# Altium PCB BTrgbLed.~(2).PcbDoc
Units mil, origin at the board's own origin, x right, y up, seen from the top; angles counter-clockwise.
Board outline 6000 x 4000 mil, 2 copper layers (Top Layer, Bottom Layer); 13 components, 12 nets, 36 pads, 0 vias.
Unrouted connection lines stored in the file: 22.
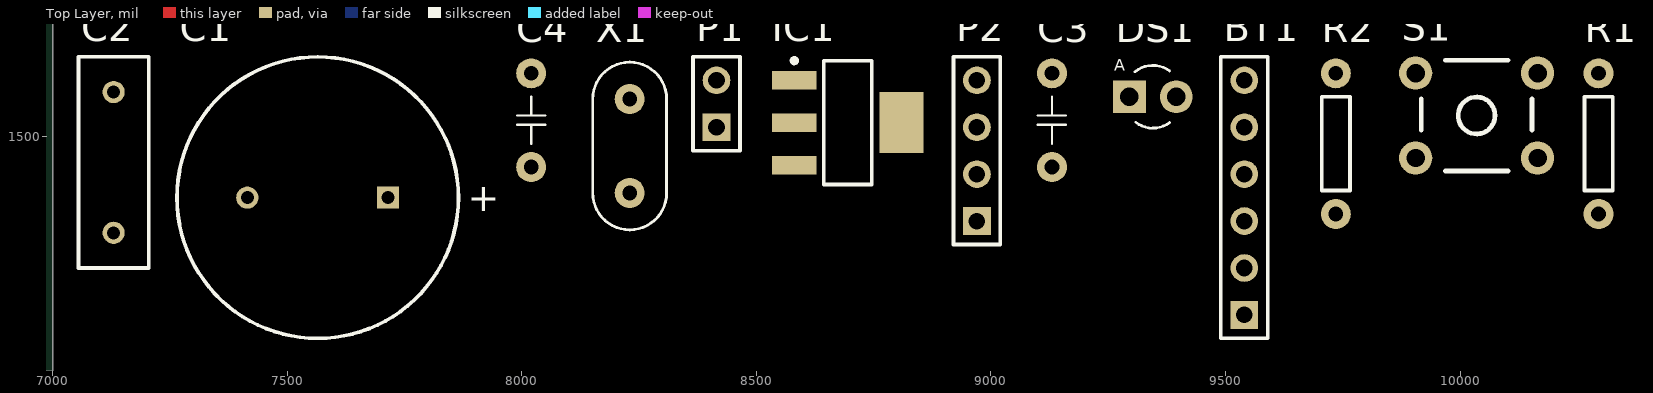
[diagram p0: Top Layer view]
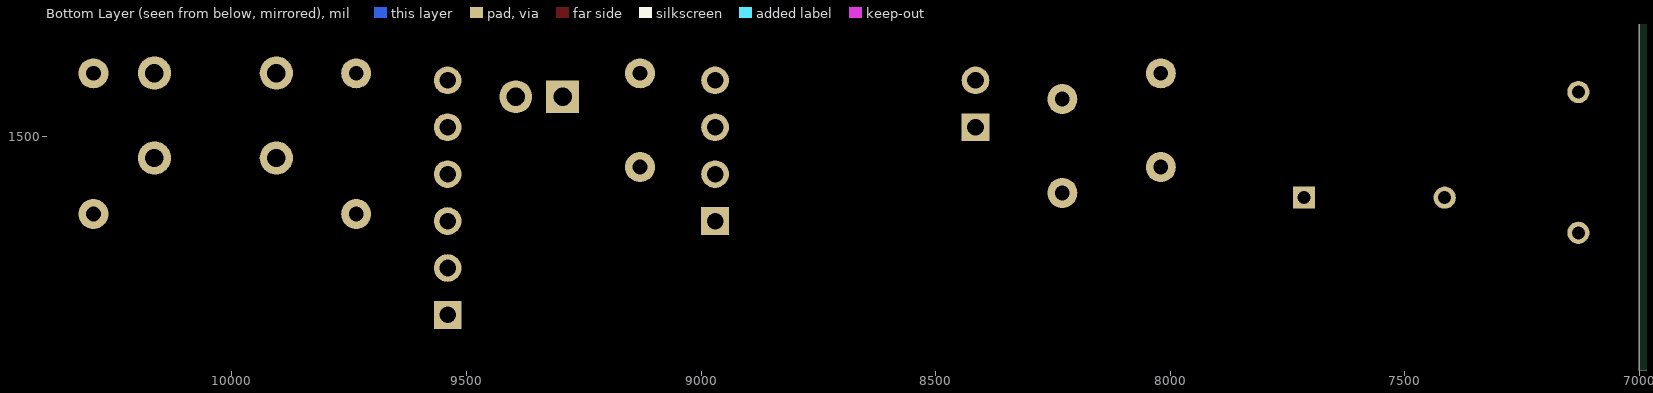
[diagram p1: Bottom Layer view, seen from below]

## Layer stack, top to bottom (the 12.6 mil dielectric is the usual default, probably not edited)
Top Layer: signal copper 1.4
Dielectric: dielectric 12.6, FR-4, Dk 4.8
Bottom Layer: signal copper 1.4

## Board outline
1000,1000 7000,1000 7000,5000 1000,5000

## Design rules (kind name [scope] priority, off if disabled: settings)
Clearance [All] p1: gap=10
PolygonConnect [All] p1: connectstyle=Relief reliefconductorwidth=10 reliefentries=4 polygonreliefangle="90 Angle"
RoomDefinition BTrgbLed [InComponentClass('BTrgbLed')] p1: confinementstyle=ConfineIn formatcopy=TRUE lockcomponents=FALSE outline 7045,1060 10365,1060 10365,1780 7045,1780
RoutingVias [All] p1: holewidth=28 width=50 viastyle="Through Hole" minholewidth=28 minwidth=50 maxholewidth=28 maxwidth=50
SilkscreenOverComponentPads [All] p1: minsilkscreentomaskgap=10
SolderMaskExpansion [All] p1: expansion=4
Width [All] p1: maxlimit=10 minlimit=10 preferedwidth=10
27 further rules are at their usual default settings.

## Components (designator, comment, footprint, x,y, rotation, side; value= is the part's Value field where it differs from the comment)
BT1 "Bluetooth" Bluetooth 9540,1120 r90 top
C1 "47uF" RB7.6-15 7565,1370 r0 top
C2 "Cap" RAD-0.3 7130,1445 r90 top
C3 "22pF" C200 9130,1535 r0 top
C4 "22pF" C200 8020,1535 r0 top
DS1 "TX-LED" LED-3mm_G 9345,1585 r0 top
IC1 "AM1117-5V" SOT-223 8695,1530 r0 top
P1 "12V" HDR1X2 8415,1520 r90 top
P2 "環形LED燈" HDR1X4 8970,1320 r90 top
R1 "10k" AXIAL-0.3 10295,1485 r90 top
R2 "220" AXIAL-0.3 9735,1485 r90 top
S1 "SW-PB" TACK6 10035,1545 r0 top
X1 "16MHz" XTAL4-8 8230,1480 r90 top

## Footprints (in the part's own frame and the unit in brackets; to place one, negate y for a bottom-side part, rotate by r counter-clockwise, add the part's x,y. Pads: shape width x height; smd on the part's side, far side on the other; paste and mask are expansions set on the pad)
AXIAL-0.3 [mil] "0.3\" Resistor; 2 Leads"
  round 64 hole 31.5: 1(-150,0) 2(150,0)
  silkscreen extent -100,-30 100,30, body extent -161,-39 165,39, height 86
Bluetooth [mm]
  rect 1.5x1.5 hole 0.9: 1(0,0)
  round 1.5 hole 0.9: 2(2.54,0) 3(5.08,0) 4(7.62,0) 5(10.16,0) 6(12.7,0)
  silkscreen extent -1.27,-1.27 13.97,1.27, body extent -1.25,-1.3 13.97,1.28, height 11
C200 [mil] "塑膠電容器"
  round 64 hole 31.5: 1(0,100) 2(0,-100)
  silkscreen extent -30,-50 30,50, body extent -41,-136 39,135, height 354
HDR1X2 [mm] "Connector; Header; 2 Position"
  rect 1.5x1.5 hole 0.9: 1(0,0)
  round 1.5 hole 0.9: 2(2.54,0)
  silkscreen extent -1.27,-1.27 3.81,1.27
HDR1X4 [mm] "Connector; Header; 4 Position"
  rect 1.5x1.5 hole 0.9: 1(0,0)
  round 1.5 hole 0.9: 2(2.54,0) 3(5.08,0) 4(7.62,0)
  silkscreen extent -1.27,-1.27 8.89,1.27
LED-3mm_G [mil] "3mm LED_Green"
  rect 70x70 hole 39: 1(-50,0)
  round 70 hole 39: 2(50,0)
  silkscreen extent -38,-67 35,67, body extent -66,-68 67,66, height 181
RAD-0.3 [mm] "Radial Cap, Thru-Hole; 2 Leads; 0.3 in Pin Spacing"
  round 1.2 hole 0.7: 1(-3.81,0) 2(3.81,0)
  silkscreen extent -5.71,-1.91 5.71,1.91
RB7.6-15 [mm] "Polarized Capacitor (Radial); 2 Leads"
  rect 1.2x1.2 hole 0.7: 1(3.81,0)
  round 1.2 hole 0.7: 2(-3.81,0)
  silkscreen extent -7.62,-7.62 7.62,7.62
SOT-223 [mm] "SOT223, 4-Leads, Body 6.7x7.3mm (max), Pitch 2.30mm, IPC Medium Density"
  rect 2.4x1 smd: 1(-2.9,2.3) 2(-2.9,0) 3(-2.9,-2.3)
  rect 2.4x3.3 smd: 2(2.9,0)
  silkscreen extent -3.02,-3.35 1.3,3.47, body extent -1.86,-3.35 1.86,3.35, height 1.8
TACK6 [mm]
  round 1.8 hole 1: 1(-3.3,2.3) 1(3.3,2.3) 2(-3.3,-2.3) 2(3.3,-2.3)
  silkscreen extent -3,-3 3,3, body extent -3,-3.01 3.08,3.04, height 8
XTAL4-8 [mil]
  round 64 hole 31.5: 1(-100,0) 2(100,0)
  silkscreen extent -179,-79 179,79, body extent -178,-80 192,79, height 157

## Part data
C1: library part "Cap Pol1", "Polarized Capacitor (Radial)"
C2: "Capacitor"
C3 C4: library part Cap, "Capacitor"
DS1: library part LED, "Typical INFRARED GaAs LED"
IC1: library part AM1117
P1: library part "Header 2", "Header, 2-Pin"
P2: library part "Header 4", "Header, 4-Pin"
R1 R2: library part Res, "Resistor"
S1: "Switch"
X1: library part XTAL, "Crystal Oscillator"

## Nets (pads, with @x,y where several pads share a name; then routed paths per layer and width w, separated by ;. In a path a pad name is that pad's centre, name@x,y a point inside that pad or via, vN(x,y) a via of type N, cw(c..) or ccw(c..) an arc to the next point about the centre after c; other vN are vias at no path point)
DI: P2.1
DO: P2.4
GND: BT1.3 C1.2 C2.2 C3.1 C4.1 DS1.2 IC1.2 P1.2 P2.3 S1.1
NetC3_2: C3.2 X1.2
NetC4_2: C4.2 X1.1
NetDS1_1: DS1.1 R2.1
NetIC1_1: IC1.1 P1.1
NetR1_2: R1.2 S1.2
NetR2_2: R2.2
RX: BT1.5
TX: BT1.4
VCC: BT1.2 C1.1 C2.1 IC1.3 P2.2 R1.1
pads on no net: BT1.1 BT1.6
